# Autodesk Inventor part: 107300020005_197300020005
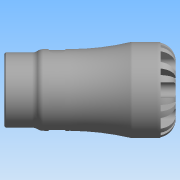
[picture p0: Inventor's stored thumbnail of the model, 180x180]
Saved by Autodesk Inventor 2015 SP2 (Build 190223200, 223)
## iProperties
Created: 2016-12
Part Number: 107300020005_197300020005
Material: Generic
Description: PLASSON FEMALE INTEGRAL BRASS THREAD 20X1/2" SERIES 1
Document SubType Name: Modeling
Designer: KIM
Density: 1 g/cm^3
Appearance: Default
Author: KIM
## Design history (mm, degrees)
derived "1073.ipt"
feature "Solid1::1073.ipt"
tag "TaggingFeature1"
body "Solid1"
other parameters: "d0" = 73, "d1" = 18.9, "d3" = 25, "d4" = 41, "d6" = 45, "d8" = 34.85, "d13" = 6.4, "d14" = 6.4, "d15" = 0, "d17" = 360 deg, "d19" = 8 deg, "d20" = 0.4, "d21" = 0.4, "d22" = 8 deg, "d24" = 0, "d26" = 360 deg, "d32" = 4.1, "d33" = 4.1, "d39" = 0.55893, "d42" = 18.631, "d43" = 31.98, "d46" = 1.66667, "d47" = 15, "d48" = 17.69945, "d50" = 4.29, "d51" = 0.41, "d54" = 7, "d55" = 4.4, "d57" = 12.544, "d58" = 0, "d68" = 360 deg, "d72" = 0.4, "d74" = 0, "d76" = 5.95, "E_" = 41, "H_" = 73, "l_" = 45, "G_" = 18.631, "l_2" = 15, "d9" = 8, "d11" = 41, "d12" = 25, "d49" = 13
